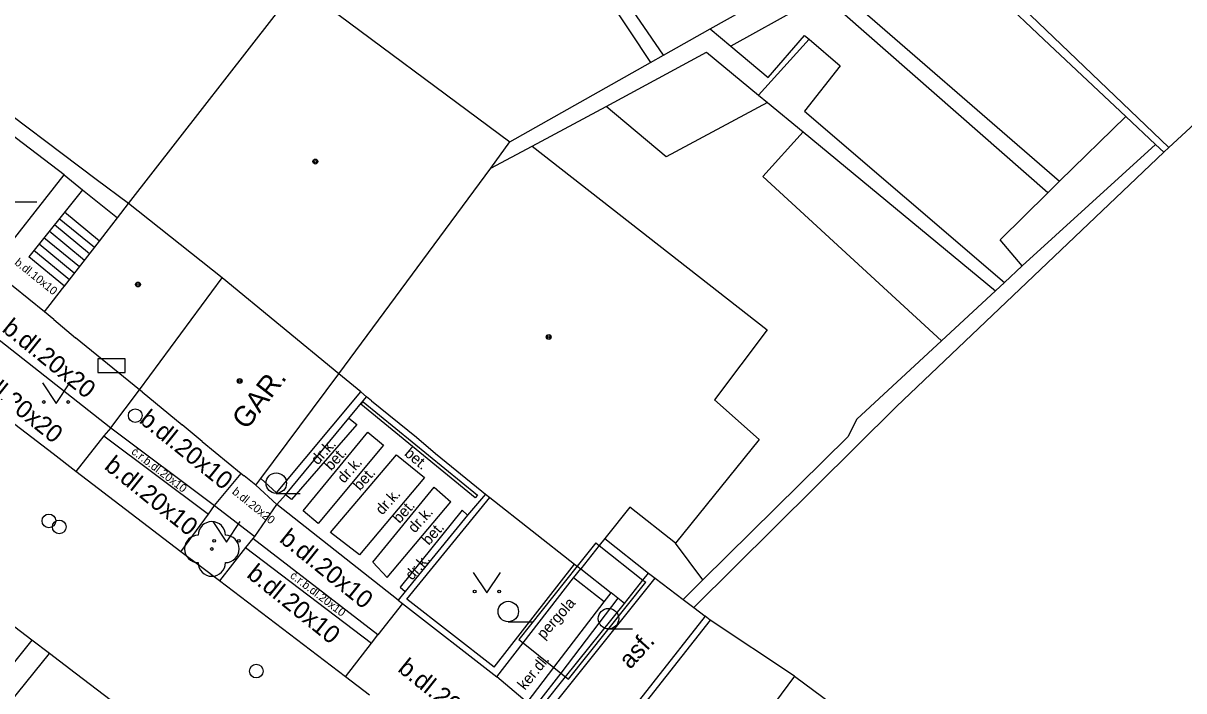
# Model space of a CAD drawing. Extents: x -595546 to -593986, y -1160845 to -1159202.
# Drawn here: x -595122.16 to -595079.69, y -1160655.11 to -1160630.67 of the extents above; entities that cross this region are included whole.
import ezdxf

# ---------------------------------------------------------------- set-up
doc = ezdxf.new("R2010")
doc.units = 0
for name, color, linetype in [('DOP - kresba z DSPS bez souradnic', 7, 'Continuous'), ('DOP - rozhrani ploch obecne', 7, 'Continuous'), ('kanalizace - povrch.  znaky - skut. velikost', 7, 'Continuous'), ('Level 22', 7, 'Continuous'), ('Level 24', 7, 'Continuous'), ('Level 28', 7, 'Continuous'), ('Level 36', 7, 'Continuous'), ('Level 39', 7, 'Continuous'), ('TM - budovy zdene_ betonove - VP', 7, 'Continuous'), ('TM - chodniky - VP', 7, 'Continuous'), ('TM - komunikace - VP', 7, 'Continuous'), ('TM - podezdivka plotu - VP', 7, 'Continuous'), ('TM - popis objektu', 7, 'Continuous'), ('TM - popis povrchu', 7, 'Continuous'), ('TM - poznamka', 7, 'Continuous'), ('TM - rozhrani mezi zpev. plochami mezi sebou - VP', 7, 'Continuous'), ('TM - rozhrani ploch obecne - VN', 7, 'Continuous'), ('TM - rozhrani ploch obecne - VP', 7, 'Continuous'), ('TM - schody - VP', 7, 'Continuous'), ('TM - vstup do budovy - zdene_ betonove', 7, 'Continuous'), ('TM - zed operna - VP', 7, 'Continuous')]:
    doc.layers.add(name, color=color, linetype=linetype)

msp = doc.modelspace()

# ---------------------------------------------------------------- linework, layer by layer
at = {"layer": 'DOP - kresba z DSPS bez souradnic'}
for points in [[(-595098.73, -1160631.85), (-595101.13, -1160628.33)], [(-595101.54, -1160628.59), (-595099.2, -1160632.11)], [(-595092.54, -1160629.24), (-595084.24, -1160636.46)], [(-595084.67, -1160636.88), (-595092.98, -1160629.57)], [(-595093.67, -1160630.08), (-595096.26, -1160631.52)], [(-595086.41, -1160629.75), (-595084.81, -1160631.27)], [(-595097.02, -1160630.88), (-595096.26, -1160631.52)], [(-595095.25, -1160633.31), (-595093.4, -1160631.26)], [(-595094.9, -1160632.66), (-595093.57, -1160631.12)], [(-595093.57, -1160631.12), (-595093.4, -1160631.26)], [(-595093.4, -1160631.26), (-595092.26, -1160632.23)], [(-595084.81, -1160631.27), (-595081.81, -1160634.09)], [(-595100.83, -1160633.72), (-595097.15, -1160631.74)], [(-595097.15, -1160631.74), (-595095.25, -1160633.31)], [(-595096.26, -1160631.52), (-595094.9, -1160632.66)], [(-595092.26, -1160632.23), (-595093.57, -1160633.9)], [(-595095.25, -1160633.31), (-595094.92, -1160633.58)], [(-595103.54, -1160635.17), (-595100.83, -1160633.72)], [(-595098.63, -1160635.57), (-595100.83, -1160633.72)], [(-595094.92, -1160633.58), (-595098.63, -1160635.57)], [(-595094.92, -1160633.58), (-595093.62, -1160634.65)], [(-595093.57, -1160633.9), (-595086.25, -1160640.17)], [(-595084.24, -1160636.46), (-595081.81, -1160634.09)], [(-595081.81, -1160634.09), (-595080.72, -1160635.11)], [(-595093.62, -1160634.65), (-595095.1, -1160636.28)], [(-595093.62, -1160634.65), (-595086.58, -1160640.47)], [(-595080.72, -1160635.11), (-595085.6, -1160639.56)], [(-595080.42, -1160635.39), (-595080.72, -1160635.11)], [(-595095.1, -1160636.28), (-595088.56, -1160642.3)], [(-595084.67, -1160636.88), (-595084.24, -1160636.46)], [(-595086.41, -1160638.6), (-595084.67, -1160636.88)], [(-595085.6, -1160639.56), (-595086.41, -1160638.6)], [(-595085.6, -1160639.56), (-595086.25, -1160640.17)], [(-595086.25, -1160640.17), (-595086.58, -1160640.47)], [(-595086.58, -1160640.47), (-595088.56, -1160642.3)], [(-595088.56, -1160642.3), (-595091.66, -1160645.17)], [(-595091.66, -1160645.17), (-595091.99, -1160645.81)], [(-595091.99, -1160645.81), (-595097.29, -1160651.05)]]:
    msp.add_lwpolyline(points, dxfattribs=at)
at = {"layer": 'DOP - rozhrani ploch obecne'}
for points in [[(-595088.38, -1160627.42), (-595080.24, -1160635.22)], [(-595097.02, -1160630.88), (-595093.24, -1160628.76)], [(-595098.73, -1160631.85), (-595097.02, -1160630.88)], [(-595104.35, -1160635.02), (-595099.2, -1160632.11)], [(-595099.2, -1160632.11), (-595098.73, -1160631.85)], [(-595080.24, -1160635.22), (-595079.14, -1160634.21)], [(-595090.2, -1160644.7), (-595080.42, -1160635.39)], [(-595080.42, -1160635.39), (-595080.24, -1160635.22)], [(-595097.62, -1160652.06), (-595090.2, -1160644.7)]]:
    msp.add_lwpolyline(points, dxfattribs=at)
at = {"layer": 'kanalizace - povrch.  znaky - skut. velikost'}
for points in [[(-595109.8, -1160644.62), (-595109.72, -1160644.53)], [(-595109.72, -1160644.53), (-595105.54, -1160647.95)], [(-595105.62, -1160648.05), (-595109.8, -1160644.62)], [(-595105.54, -1160647.95), (-595105.62, -1160648.05)]]:
    msp.add_lwpolyline(points, dxfattribs=at)
at = {"layer": 'Level 22'}
msp.add_circle((-595115.26, -1160649.92), 0.05, dxfattribs=at)
for centre, start, end in [((-595115.26, -1160649.42), 0, 180), ((-595115.76, -1160649.92), 90, 270), ((-595114.76, -1160649.92), 270, 90), ((-595115.26, -1160650.42), 180, 0)]:
    msp.add_arc(centre, 0.5, start, end, dxfattribs=at)
at = {"layer": 'Level 24'}
msp.add_lwpolyline([(-595119.428, -1160643.459), (-595118.428, -1160643.459), (-595118.428, -1160642.959), (-595119.428, -1160642.959)], close=True, dxfattribs=at)
at = {"layer": 'Level 28'}
for centre in [(-595118.06, -1160645.04), (-595121.22, -1160648.89), (-595120.84, -1160649.11), (-595113.63, -1160654.39)]:
    msp.add_circle(centre, 0.25, dxfattribs=at)
at = {"layer": 'Level 36'}
for p, q in [((-595122.54, -1160637.215), (-595121.665, -1160637.215)), ((-595112.9, -1160647.885), (-595112.025, -1160647.885)), ((-595104.41, -1160652.585), (-595103.535, -1160652.585)), ((-595100.74, -1160652.845), (-595099.865, -1160652.845))]:
    msp.add_line(p, q, dxfattribs=at)
for points in [[(-595121.46, -1160643.84), (-595120.96, -1160644.59), (-595120.46, -1160643.84)], [(-595115.22, -1160648.92), (-595114.72, -1160649.67), (-595114.22, -1160648.92)], [(-595105.69, -1160650.78), (-595105.19, -1160651.53), (-595104.69, -1160650.78)]]:
    msp.add_lwpolyline(points, dxfattribs=at)
for centre, radius in [((-595121.41, -1160644.54), 0.05), ((-595120.511, -1160644.54), 0.05), ((-595112.9, -1160647.51), 0.375), ((-595115.17, -1160649.62), 0.05), ((-595114.271, -1160649.62), 0.05), ((-595105.64, -1160651.48), 0.05), ((-595104.741, -1160651.48), 0.05), ((-595104.41, -1160652.21), 0.375), ((-595100.74, -1160652.47), 0.375)]:
    msp.add_circle(centre, radius, dxfattribs=at)
at = {"layer": 'Level 39'}
for centre, radius in [((-595111.47, -1160635.74), 0.09), ((-595111.47, -1160635.74), 0.0398), ((-595117.96, -1160640.24), 0.09), ((-595117.96, -1160640.24), 0.0398), ((-595102.93, -1160642.16), 0.09), ((-595102.93, -1160642.16), 0.0398), ((-595114.24, -1160643.77), 0.09), ((-595114.24, -1160643.77), 0.0398)]:
    msp.add_circle(centre, radius, dxfattribs=at)
at = {"layer": 'TM - budovy zdene_ betonove - VP'}
for points in [[(-595118.31, -1160637.28), (-595112.08, -1160629.26)], [(-595111.78, -1160629.49), (-595104.35, -1160635.02)], [(-595119.49, -1160636.39), (-595123.83, -1160633.13)], [(-595105.05, -1160635.98), (-595104.35, -1160635.02)], [(-595105.05, -1160635.98), (-595103.54, -1160635.17)], [(-595103.54, -1160635.17), (-595094.94, -1160641.9)], [(-595110.61, -1160643.51), (-595105.05, -1160635.98)], [(-595118.31, -1160637.28), (-595119.49, -1160636.39)], [(-595118.71, -1160637.8), (-595118.31, -1160637.28)], [(-595114.88, -1160639.99), (-595118.31, -1160637.28)], [(-595119.13, -1160638.34), (-595118.71, -1160637.8)], [(-595120.65, -1160640.3), (-595119.37, -1160638.65), (-595119.13, -1160638.34)], [(-595120.72, -1160640.39), (-595120.65, -1160640.3)], [(-595117.91, -1160644.09), (-595114.88, -1160639.99)], [(-595110.61, -1160643.51), (-595114.88, -1160639.99)], [(-595121.38, -1160641.24), (-595120.72, -1160640.39)], [(-595121.04, -1160641.52), (-595121.38, -1160641.24)], [(-595094.94, -1160641.9), (-595096.86, -1160644.46)], [(-595117.91, -1160644.09), (-595120.25, -1160642.19)], [(-595113.46, -1160647.34), (-595110.61, -1160643.51)], [(-595109.81, -1160644.17), (-595110.61, -1160643.51)], [(-595117.81, -1160644.17), (-595117.91, -1160644.09)], [(-595109.6, -1160644.35), (-595109.81, -1160644.17)], [(-595109.42, -1160644.5), (-595109.6, -1160644.35)], [(-595096.86, -1160644.46), (-595095.23, -1160645.91)], [(-595115.61, -1160645.98), (-595116.34, -1160645.38)], [(-595107.77, -1160645.83), (-595107.07, -1160646.43)], [(-595095.23, -1160645.91), (-595098.29, -1160649.71)], [(-595113.65, -1160647.59), (-595114.08, -1160647.24)], [(-595113.65, -1160647.59), (-595113.46, -1160647.34)], [(-595105.38, -1160647.8), (-595105.24, -1160647.91)], [(-595105.24, -1160647.91), (-595105.08, -1160648.04)], [(-595105.08, -1160648.04), (-595101.99, -1160650.47)], [(-595099.96, -1160648.39), (-595100.83, -1160649.48)], [(-595098.29, -1160649.71), (-595099.96, -1160648.39)], [(-595100.88, -1160649.54), (-595101.08, -1160649.79)], [(-595100.83, -1160649.48), (-595100.88, -1160649.54)], [(-595101.08, -1160649.79), (-595101.76, -1160650.65)], [(-595101.99, -1160650.47), (-595101.89, -1160650.55)], [(-595101.89, -1160650.55), (-595101.76, -1160650.65)], [(-595097.02, -1160652.52), (-595100.85, -1160657.4)], [(-595093.93, -1160654.58), (-595097.02, -1160652.52)], [(-595093.93, -1160654.58), (-595097.87, -1160659.9)], [(-595093.93, -1160654.58), (-595091.25, -1160656.57)]]:
    msp.add_lwpolyline(points, dxfattribs=at)
at = {"layer": 'TM - chodniky - VP'}
for points in [[(-595121.38, -1160641.24), (-595122.53, -1160640.31), (-595123.37, -1160639.66)], [(-595124.43, -1160641.18), (-595118.95, -1160645.49)], [(-595119.21, -1160645.78), (-595120.23, -1160647.08)], [(-595118.95, -1160645.49), (-595119.21, -1160645.78)], [(-595115.38, -1160648.65), (-595115.16, -1160648.33)], [(-595115.16, -1160648.33), (-595113.69, -1160649.46)], [(-595108.44, -1160651.79), (-595112.88, -1160648.29)], [(-595116.39, -1160650.02), (-595115.38, -1160648.65)], [(-595113.76, -1160649.54), (-595114.02, -1160649.86)], [(-595113.69, -1160649.46), (-595113.76, -1160649.54)], [(-595114.02, -1160649.86), (-595114.98, -1160651.09)], [(-595121.84, -1160653.26), (-595123.26, -1160655.01)], [(-595122.62, -1160655.51), (-595121.2, -1160653.75)], [(-595103.72, -1160655.54), (-595104.83, -1160654.6)]]:
    msp.add_lwpolyline(points, dxfattribs=at)
at = {"layer": 'TM - komunikace - VP'}
for points in [[(-595121.06, -1160646.44), (-595123.05, -1160644.93)], [(-595120.23, -1160647.08), (-595121.06, -1160646.44)], [(-595116.39, -1160650.02), (-595120.23, -1160647.08)], [(-595121.84, -1160653.26), (-595127.35, -1160649.06)], [(-595115.67, -1160650.56), (-595116.39, -1160650.02)], [(-595114.98, -1160651.09), (-595115.67, -1160650.56)], [(-595110.37, -1160654.6), (-595114.98, -1160651.09)], [(-595121.2, -1160653.75), (-595121.84, -1160653.26)], [(-595120.26, -1160654.46), (-595121.2, -1160653.75)], [(-595116.88, -1160657.04), (-595120.26, -1160654.46)], [(-595109.49, -1160655.27), (-595110.37, -1160654.6)]]:
    msp.add_lwpolyline(points, dxfattribs=at)
at = {"layer": 'TM - podezdivka plotu - VP'}
for points in [[(-595110.25, -1160645.13), (-595109.6, -1160644.35)], [(-595112.56, -1160647.94), (-595110.25, -1160645.13)], [(-595113.65, -1160647.59), (-595112.88, -1160648.29)], [(-595112.88, -1160648.29), (-595112.56, -1160647.94)], [(-595105.24, -1160647.91), (-595105.9, -1160648.68)], [(-595105.9, -1160648.68), (-595108.18, -1160651.48)], [(-595102.02, -1160650.98), (-595101.76, -1160650.65)], [(-595099.28, -1160650.81), (-595099.04, -1160650.99)], [(-595103.86, -1160653.36), (-595102.02, -1160650.98)], [(-595102.89, -1160655.81), (-595099.04, -1160650.99)], [(-595108.18, -1160651.48), (-595108.44, -1160651.79)], [(-595100.9, -1160651.86), (-595100.64, -1160651.53)], [(-595100.4, -1160651.72), (-595100.64, -1160651.53)], [(-595108.44, -1160651.79), (-595108.28, -1160651.91)], [(-595108.28, -1160651.91), (-595104.83, -1160654.6)], [(-595102.74, -1160654.26), (-595100.9, -1160651.86)], [(-595097.02, -1160652.52), (-595097.2, -1160652.38)], [(-595104.83, -1160654.6), (-595103.86, -1160653.36)], [(-595103.72, -1160655.54), (-595102.74, -1160654.26)]]:
    msp.add_lwpolyline(points, dxfattribs=at)
at = {"layer": 'TM - rozhrani mezi zpev. plochami mezi sebou - VP'}
for points in [[(-595123.37, -1160639.66), (-595120.66, -1160636.23)], [(-595118.95, -1160645.49), (-595117.91, -1160644.09)], [(-595109.95, -1160645.36), (-595112.34, -1160648.11)], [(-595110.25, -1160645.13), (-595109.95, -1160645.36)], [(-595119.21, -1160645.78), (-595115.38, -1160648.65)], [(-595118.95, -1160645.49), (-595115.16, -1160648.33)], [(-595111.92, -1160648.52), (-595109.55, -1160645.64)], [(-595109.55, -1160645.64), (-595108.98, -1160646.12)], [(-595108.98, -1160646.12), (-595111.37, -1160648.99)], [(-595110.91, -1160649.32), (-595108.5, -1160646.48)], [(-595108.5, -1160646.48), (-595107.48, -1160647.3)], [(-595115.16, -1160648.33), (-595114.18, -1160647.16)], [(-595107.48, -1160647.3), (-595109.85, -1160650.13)], [(-595112.34, -1160648.11), (-595112.56, -1160647.94)], [(-595109.36, -1160650.4), (-595107.12, -1160647.66)], [(-595107.12, -1160647.66), (-595106.51, -1160648.2)], [(-595113.69, -1160649.46), (-595112.88, -1160648.29)], [(-595108.84, -1160650.97), (-595106.51, -1160648.2)], [(-595111.37, -1160648.99), (-595111.92, -1160648.52)], [(-595106.1, -1160648.5), (-595108.37, -1160651.32)], [(-595105.9, -1160648.68), (-595106.1, -1160648.5)], [(-595109.18, -1160653.06), (-595113.76, -1160649.54)], [(-595109.85, -1160650.13), (-595110.91, -1160649.32)], [(-595114.02, -1160649.86), (-595109.42, -1160653.37)], [(-595108.84, -1160650.97), (-595109.36, -1160650.4)], [(-595108.37, -1160651.32), (-595108.18, -1160651.48)], [(-595108.28, -1160651.91), (-595109.18, -1160653.06)], [(-595110.37, -1160654.6), (-595109.42, -1160653.37)], [(-595109.42, -1160653.37), (-595109.18, -1160653.06)]]:
    msp.add_lwpolyline(points, dxfattribs=at)
at = {"layer": 'TM - rozhrani ploch obecne - VN'}
for points in [[(-595101.2, -1160649.69), (-595101.89, -1160650.55)], [(-595101.2, -1160649.69), (-595101.08, -1160649.79)], [(-595101.08, -1160649.79), (-595099.48, -1160651.06)], [(-595101.89, -1160650.55), (-595104.02, -1160653.23)], [(-595102.2, -1160654.69), (-595099.38, -1160651.14)], [(-595099.48, -1160651.06), (-595099.38, -1160651.14)], [(-595104.02, -1160653.23), (-595103.86, -1160653.36)], [(-595103.86, -1160653.36), (-595102.74, -1160654.26)], [(-595102.74, -1160654.26), (-595102.49, -1160654.46)], [(-595102.49, -1160654.46), (-595102.31, -1160654.6)], [(-595102.31, -1160654.6), (-595102.2, -1160654.69)]]:
    msp.add_lwpolyline(points, dxfattribs=at)
at = {"layer": 'TM - rozhrani ploch obecne - VP'}
for points in [[(-595120.66, -1160636.23), (-595122.92, -1160634.5)], [(-595120.66, -1160636.23), (-595119.99, -1160636.77)], [(-595119.99, -1160636.77), (-595121.96, -1160639.23)], [(-595119.99, -1160636.77), (-595118.71, -1160637.8)], [(-595120.65, -1160640.3), (-595121.96, -1160639.23)], [(-595100.88, -1160649.54), (-595099.28, -1160650.81)], [(-595097.29, -1160651.05), (-595098.29, -1160649.71)], [(-595101.76, -1160650.65), (-595100.64, -1160651.53)], [(-595100.9, -1160651.86), (-595102.02, -1160650.98)], [(-595099.04, -1160650.99), (-595098.01, -1160651.77)], [(-595098.01, -1160651.77), (-595097.29, -1160651.05)], [(-595100.16, -1160651.91), (-595100.4, -1160651.72)], [(-595098.01, -1160651.77), (-595097.62, -1160652.06)], [(-595097.62, -1160652.06), (-595097.2, -1160652.38)]]:
    msp.add_lwpolyline(points, dxfattribs=at)
at = {"layer": 'TM - schody - VP'}
for points in [[(-595119.37, -1160638.65), (-595120.65, -1160637.59)], [(-595119.74, -1160639.12), (-595121.02, -1160638.06)], [(-595119.55, -1160638.88), (-595120.84, -1160637.83)], [(-595120.1, -1160639.59), (-595121.4, -1160638.53)], [(-595119.92, -1160639.36), (-595121.21, -1160638.29)], [(-595120.47, -1160640.07), (-595121.77, -1160639)], [(-595120.29, -1160639.83), (-595121.58, -1160638.76)]]:
    msp.add_lwpolyline(points, dxfattribs=at)
at = {"layer": 'TM - vstup do budovy - zdene_ betonove'}
for points in [[(-595121.04, -1160641.52), (-595120.25, -1160642.19)], [(-595117.81, -1160644.17), (-595116.34, -1160645.38)], [(-595109.42, -1160644.5), (-595107.77, -1160645.83)], [(-595115.61, -1160645.98), (-595114.18, -1160647.16)], [(-595107.07, -1160646.43), (-595105.38, -1160647.8)], [(-595114.18, -1160647.16), (-595114.08, -1160647.24)]]:
    msp.add_lwpolyline(points, dxfattribs=at)
at = {"layer": 'TM - zed operna - VP'}
for points in [[(-595112.89, -1160647.86), (-595109.81, -1160644.17)], [(-595113.46, -1160647.34), (-595112.89, -1160647.86)], [(-595104.92, -1160654.25), (-595108.12, -1160651.76), (-595105.08, -1160648.04)], [(-595104.92, -1160654.25), (-595101.99, -1160650.47)], [(-595099.48, -1160651.06), (-595099.28, -1160650.81)], [(-595100.16, -1160651.91), (-595099.48, -1160651.06)], [(-595100.4, -1160651.72), (-595102.49, -1160654.46)], [(-595102.31, -1160654.6), (-595100.16, -1160651.91)], [(-595097.2, -1160652.38), (-595101.03, -1160657.26)], [(-595102.49, -1160654.46), (-595103.3, -1160655.51)], [(-595103.13, -1160655.63), (-595102.31, -1160654.6)]]:
    msp.add_lwpolyline(points, dxfattribs=at)

# ---------------------------------------------------------------- texts
at = {"layer": 'TM - popis objektu'}
msp.add_text('GAR.', height=0.75, rotation=52.19, dxfattribs=at).set_placement((-595113.99, -1160645.59))
at = {"layer": 'TM - popis povrchu'}
for s, height, rotation, p in [('b.dl.10x10', 0.3, 320.9628, (-595122.5, -1160639.48)), ('b.dl.20x20', 0.65, 321.1457, (-595122.97, -1160641.93)), ('b.dl.20x20', 0.65, 321.1457, (-595124.17, -1160643.57)), ('b.dl.20x10', 0.65, 321.1457, (-595117.95, -1160645.27)), ('č.r.b.dl.20x10', 0.3, 322.5939, (-595118.23, -1160646.41)), ('dr.k.', 0.4, 48.0128, (-595111.38, -1160646.87)), ('bet.', 0.4, 319.8414, (-595108.24, -1160646.47)), ('b.dl.20x10', 0.65, 321.1457, (-595119.23, -1160646.96)), ('bet.', 0.4, 48.0128, (-595110.89, -1160647.08)), ('dr.k.', 0.4, 48.0128, (-595110.42, -1160647.54)), ('bet.', 0.4, 48.0128, (-595109.84, -1160647.81)), ('b.dl.20x20', 0.3, 321.1457, (-595114.54, -1160647.87)), ('dr.k.', 0.4, 48.0128, (-595109.02, -1160648.7)), ('bet.', 0.4, 48.0128, (-595108.39, -1160649.01)), ('dr.k.', 0.4, 48.0128, (-595107.83, -1160649.36)), ('b.dl.20x10', 0.65, 321.1457, (-595112.82, -1160649.63)), ('bet.', 0.4, 48.0128, (-595107.32, -1160649.81)), ('b.dl.20x10', 0.65, 321.1457, (-595114.02, -1160650.92)), ('dr.k.', 0.4, 48.0128, (-595107.93, -1160651.09)), ('č.r.b.dl.20x10', 0.3, 322.5939, (-595112.42, -1160650.95)), ('asf.', 0.65, 47.7383, (-595099.95, -1160654.35)), ('b.dl.20x20', 0.65, 321.1457, (-595108.49, -1160654.37)), ('ker.dl.', 0.4, 50.9433, (-595103.8, -1160655.11))]:
    msp.add_text(s, height=height, rotation=rotation, dxfattribs=at).set_placement(p)
at = {"layer": 'TM - poznamka'}
msp.add_text('pergola', height=0.4, rotation=48.4709, dxfattribs=at).set_placement((-595103.11, -1160653.25))

doc.saveas('drawing.dxf')
